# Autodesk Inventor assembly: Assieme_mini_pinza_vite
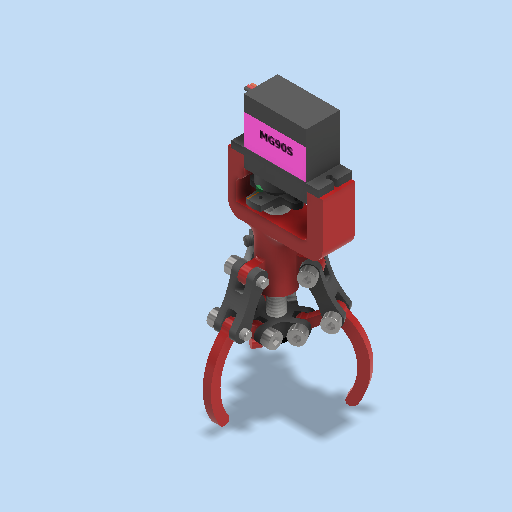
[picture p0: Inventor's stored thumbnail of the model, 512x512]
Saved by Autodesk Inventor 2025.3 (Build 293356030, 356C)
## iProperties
Created: 2026-05
Part Number: Assieme_mini_pinza_vite
Document SubType Name: Assembly
Designer: Ryzen5700u
Author: Ryzen5700u
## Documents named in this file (12)
- C:\Users\R5800u\Desktop\mini_pinza_vite\Assieme_mini_pinza_vite.iam
- C:\Users\R5800u\Desktop\mini_pinza_vite\Parte1.ipt
- C:\Users\R5800u\Desktop\mini_pinza_vite\Parte2.ipt
- C:\Users\R5800u\Desktop\mini_pinza_vite\Parte4.ipt
- C:\Users\R5800u\Documents\Inventor\Content Center Files\R2025\it-IT\AS 1420\AS 1420 - 1973 - M3 x 10.ipt
- C:\Users\R5800u\Desktop\mini_pinza_vite\vite.ipt
- C:\Users\R5800u\Desktop\mini_pinza_vite\vite3.ipt
- C:\Users\R5800u\Desktop\mini_pinza_vite\dado.ipt
- C:\Users\R5800u\Documents\Inventor\Content Center Files\R2025\it-IT\AS 1427(08)\AS 1427 - M2,5 x 5(6) I.ipt
- C:\Users\R5800u\Desktop\mini_pinza_vite\rondella.ipt
- C:\Users\R5800u\Desktop\mini_pinza_vite\MG90_ldb_v2.ipt
- C:\Users\R5800u\Desktop\mini_pinza_vite\RCXAZ_9g doppio.ipt
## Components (27 placed, 11 different names)
1. Parte1:1
2. AS 1420 - Metrico M3 x 10:2
3. AS 1420 - Metrico M3 x 10:4
4. AS 1420 - Metrico M3 x 10:5
5. AS 1420 - Metrico M3 x 10:6
6. vite:1
7. vite3:1 — Coincidente:12, Allineato:1, Coincidente:18, Allineato:2
8. dado:1 — Coincidente:8, Coincidente:9, Coincidente:11, Rotazionale:11, Rotazionale:12, Rotazionale:13
9. AS 1420 - Metrico M3 x 10:16 — Rotazionale:11
10. AS 1420 - Metrico M3 x 10:17 — Rotazionale:12
11. AS 1420 - Metrico M3 x 10:18 — Rotazionale:13
12. AS 1427 Z - Metrico M2,5 x 5:1 — Coincidente:18, Rotazionale:14
13. rondella:1 — Rotazionale:14
14. MG90_ldb_v2:1 — Coincidente:19, Angolo:1, Coincidente:20, Rotazionale:15
15. RCXAZ_9g doppio:1 — Rotazionale:15
16. Parte4:1 — Coincidente:4, Coincidente:5, Coincidente:6, Rotazionale:6, Rotazionale:10, Coincidente:10
17. AS 1420 - Metrico M3 x 10:11 — Rotazionale:10
18. AS 1420 - Metrico M3 x 10:7 — Rotazionale:6
19. Parte2:1 — Coincidente:6, Coincidente:8, Coincidente:9, Coincidente:10
20. Parte4:2
21. AS 1420 - Metrico M3 x 10:12
22. AS 1420 - Metrico M3 x 10:13
23. Parte2:2
24. Parte4:3
25. AS 1420 - Metrico M3 x 10:14
26. AS 1420 - Metrico M3 x 10:15
27. Parte2:3
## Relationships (21: Mate 11, RevoluteJoint 7, Flush 2, Angle 1)
- Coincidente:4 [Mate]: Parte4:1
- Coincidente:5 [Mate]: Parte4:1
- Coincidente:6 [Mate]: Parte4:1 ↔ Parte2:1
- Rotazionale:6 [RevoluteJoint]: Parte4:1 ↔ AS 1420 - Metrico M3 x 10:7
- Rotazionale:10 [RevoluteJoint]: Parte4:1 ↔ AS 1420 - Metrico M3 x 10:11
- Coincidente:8 [Mate]: dado:1 ↔ Parte2:1
- Coincidente:9 [Mate]: dado:1 ↔ Parte2:1
- Coincidente:10 [Mate]: Parte4:1 ↔ Parte2:1
- Coincidente:11 [Mate]: dado:1
- Coincidente:12 [Mate]: vite3:1
- Allineato:1 [Flush]: vite3:1
- Rotazionale:11 [RevoluteJoint]: dado:1 ↔ AS 1420 - Metrico M3 x 10:16
- Rotazionale:12 [RevoluteJoint]: dado:1 ↔ AS 1420 - Metrico M3 x 10:17
- Rotazionale:13 [RevoluteJoint]: dado:1 ↔ AS 1420 - Metrico M3 x 10:18
- Coincidente:18 [Mate]: vite3:1 ↔ AS 1427 Z - Metrico M2,5 x 5:1
- Rotazionale:14 [RevoluteJoint]: AS 1427 Z - Metrico M2,5 x 5:1 ↔ rondella:1
- Coincidente:19 [Mate]: MG90_ldb_v2:1
- Angolo:1 [Angle]: MG90_ldb_v2:1
- Allineato:2 [Flush]: vite3:1
- Coincidente:20 [Mate]: MG90_ldb_v2:1
- Rotazionale:15 [RevoluteJoint]: MG90_ldb_v2:1 ↔ RCXAZ_9g doppio:1
